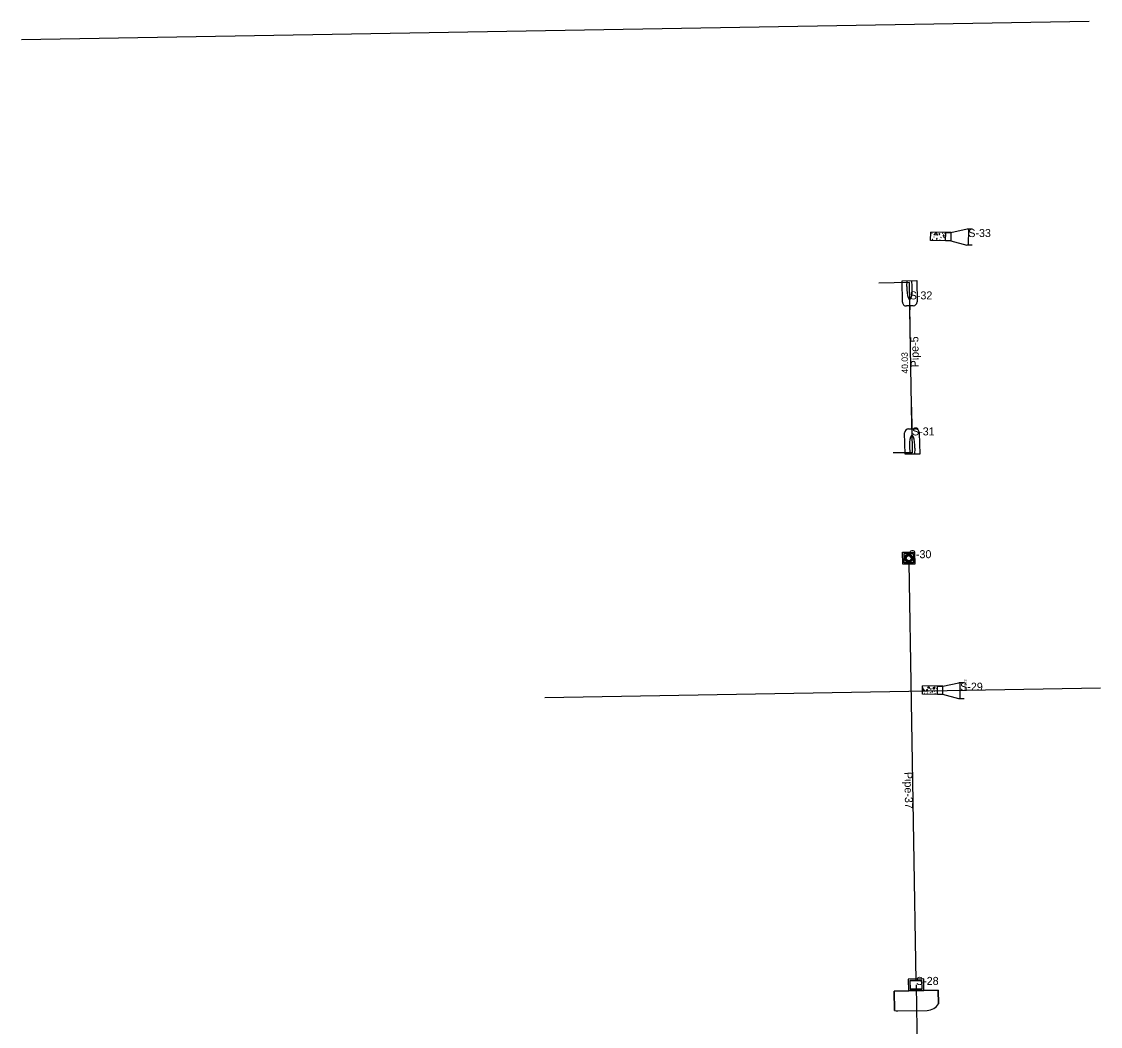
# Model space of a CAD drawing. Extents: x 925371 to 925937, y 853654 to 858024.
# Drawn here: x 925419.2 to 925823.6, y 855352.2 to 855728.9 of the extents above; entities that cross this region are included whole.
import ezdxf

# ---------------------------------------------------------------- set-up
doc = ezdxf.new("R2010")
doc.units = 0
for name, color, linetype in [('DitchPavt', 7, 'Continuous'), ('GPKDrBack_dp', 7, 'Continuous'), ('GPKDrBottom_dp', 7, 'Continuous'), ('GPKDrCellIns_dp', 7, 'Continuous'), ('GPKDrCentroid_dp', 7, 'Continuous'), ('GPKDrFront_dp', 7, 'Continuous'), ('GPKDrPipe_dp', 7, 'Continuous'), ('GPKDrPipeCir_dp', 7, 'Continuous'), ('InletBottomP', 7, 'Continuous'), ('InletClosedFlume', 7, 'Continuous'), ('InletDBI', 7, 'Continuous'), ('Manhole', 7, 'Continuous'), ('MES', 7, 'Continuous'), ('Miscellaneous5', 7, 'Continuous'), ('Miscellaneous6', 7, 'Continuous'), ('NonPlottingEle_dp', 7, 'Continuous'), ('PipeCulvert', 7, 'Continuous'), ('PipeCulvertSS', 7, 'Continuous')]:
    doc.layers.add(name, color=color, linetype=linetype)

msp = doc.modelspace()

# ---------------------------------------------------------------- linework, layer by layer
at = {"layer": 'DitchPavt'}
for p, q in [((925767.56, 855649.81), (925759.96, 855649.94)), ((925760.38, 855649.56), (925760.5, 855649.65)), ((925762.04, 855649.9), (925762.53, 855648.87)), ((925764.63, 855649.52), (925764.41, 855649.61)), ((925765.51, 855649.42), (925765.29, 855649.51)), ((925761.12, 855648.19), (925761.26, 855648.29)), ((925763.97, 855647.93), (925763.75, 855648.02)), ((925765.11, 855647.92), (925764.91, 855648.01)), ((925765.46, 855646.8), (925765.51, 855646.82)), ((925765.51, 855647.69), (925765.52, 855647.7)), ((925757.15, 855477.88), (925756.88, 855478.01)), ((925757.24, 855478.98), (925757.4, 855479.07)), ((925757.53, 855477.11), (925757.68, 855477.22)), ((925758.77, 855477.19), (925758.57, 855477.28)), ((925759.77, 855477.33), (925759.91, 855477.43)), ((925759.84, 855478.54), (925760, 855478.63)), ((925760.03, 855478.81), (925760.18, 855478.9)), ((925761.3, 855478.5), (925761.09, 855478.59)), ((925761.61, 855477.83), (925761.39, 855477.92)), ((925762.11, 855478.84), (925762.26, 855478.97)), ((925751.56, 855365.58), (925746.26, 855365.49)), ((925746.26, 855365.49), (925746.39, 855358.21)), ((925757.39, 855365.68), (925751.56, 855365.58)), ((925747.6, 855358.08), (925758.6, 855358.26))]:
    msp.add_line(p, q, dxfattribs=at)
for points in [[(925765.51, 855646.8), (925759.91, 855646.9), (925759.96, 855649.94)], [(925762.53, 855648.87), (925761.16, 855649.04), (925762.01, 855649.91)], [(925763.11, 855649.18), (925763.22, 855649.15), (925763.32, 855649.23), (925763.29, 855649.34), (925763.24, 855649.42), (925763.17, 855649.42), (925763.06, 855649.38), (925763.01, 855649.29), (925763.06, 855649.2), (925763.11, 855649.18)], [(925760.64, 855647.03), (925760.67, 855647.06), (925760.7, 855647.15), (925760.65, 855647.25), (925760.61, 855647.28), (925760.51, 855647.25), (925760.49, 855647.12), (925760.52, 855647.06), (925760.58, 855647.03), (925760.64, 855647.03)], [(925762.23, 855647.4), (925762.32, 855647.49), (925762.32, 855647.59), (925762.21, 855647.65), (925762.1, 855647.55), (925762.14, 855647.49), (925762.15, 855647.43), (925762.23, 855647.4), (925762.2, 855647.4)], [(925763.25, 855646.84), (925763.47, 855647.14), (925763.57, 855646.83)], [(925764.81, 855648.46), (925764.96, 855648.51), (925765.04, 855648.7), (925764.92, 855648.91), (925764.77, 855648.91), (925764.64, 855648.83), (925764.63, 855648.75), (925764.66, 855648.61), (925764.7, 855648.5), (925764.81, 855648.46)], [(925762.46, 855476.72), (925756.86, 855476.82), (925756.92, 855479.86)], [(925764.51, 855479.73), (925756.92, 855479.86)], [(925759.45, 855478.89), (925758.83, 855479.19), (925759.18, 855479.67), (925759.45, 855478.89)], [(925761.25, 855478.7), (925760.96, 855479.23), (925761.53, 855479.49), (925761.25, 855478.7)], [(925762.33, 855479.77), (925762.32, 855479.75), (925762.36, 855479.69), (925762.42, 855479.66), (925762.48, 855479.66)], [(925762.48, 855479.66), (925762.51, 855479.69), (925762.51, 855479.7)], [(925756.89, 855478.56), (925757.08, 855478.63), (925757.15, 855477.88)], [(925757.74, 855478.17), (925757.79, 855478.3), (925757.72, 855478.3), (925757.65, 855478.27), (925757.68, 855478.19), (925757.74, 855478.17)], [(925758.43, 855478.12), (925758.7, 855478.07), (925758.79, 855478.18), (925758.79, 855478.25), (925758.78, 855478.43), (925758.6, 855478.5), (925758.42, 855478.45), (925758.38, 855478.34), (925758.38, 855478.22), (925758.43, 855478.12)], [(925760.5, 855477.56), (925760.61, 855477.63), (925760.62, 855477.72), (925760.58, 855477.78), (925760.55, 855477.78), (925760.45, 855477.75), (925760.41, 855477.69), (925760.45, 855477.63), (925760.5, 855477.56)], [(925760.87, 855478.88), (925760.93, 855478.93), (925760.96, 855479.01), (925760.93, 855479.07), (925760.87, 855479.09), (925760.79, 855479.07), (925760.71, 855479.04), (925760.74, 855478.94), (925760.78, 855478.88), (925760.87, 855478.88)], [(925761.68, 855476.74), (925761.67, 855476.8), (925761.59, 855476.9), (925761.51, 855476.86), (925761.47, 855476.83), (925761.44, 855476.77), (925761.44, 855476.74)], [(925762.49, 855478.37), (925762.41, 855478.41), (925762.49, 855478.44)], [(925746.26, 855365.49), (925762.76, 855365.77), (925762.85, 855360.76)], [(925746.39, 855358.21), (925746.26, 855365.49)], [(925762.85, 855360.76), (925762.76, 855365.77), (925757.39, 855365.68)]]:
    msp.add_lwpolyline(points, dxfattribs=at)
for centre, start, end in [((925747.52, 855363.08), 256.9322, 270.9573), ((925758.52, 855363.26), 270.9573, 329.9964)]:
    msp.add_arc(centre, 5, start, end, dxfattribs=at)
at = {"layer": 'GPKDrBack_dp'}
for p, q in [((925767.53, 855648.28), (925767.53, 855648.28)), ((925751.95, 855631.82), (925751.95, 855631.82)), ((925753.06, 855566.77), (925753.06, 855566.77)), ((925753.22, 855527.8), (925753.22, 855527.8)), ((925753.47, 855527.8), (925753.47, 855527.8)), ((925764.49, 855478.21), (925764.49, 855478.21)), ((925754.4, 855369.96), (925754.4, 855369.96)), ((925757.36, 855367.84), (925757.36, 855367.84))]:
    msp.add_line(p, q, dxfattribs=at)
at = {"layer": 'GPKDrBottom_dp'}
for p, q in [((925774.03, 855648.17), (925774.03, 855648.17)), ((925752.07, 855624.79), (925752.07, 855624.79)), ((925752.93, 855573.8), (925752.93, 855573.8)), ((925749.94, 855529.49), (925749.94, 855529.49)), ((925751, 855528.47), (925751, 855528.47)), ((925751.69, 855529.52), (925751.69, 855529.52)), ((925751.7, 855528.77), (925751.7, 855528.77)), ((925752.41, 855528.49), (925752.41, 855528.49)), ((925753.44, 855529.55), (925753.44, 855529.55)), ((925749.97, 855527.74), (925749.97, 855527.74)), ((925750, 855525.99), (925750, 855525.99)), ((925750.72, 855527.75), (925750.72, 855527.75)), ((925751.02, 855527.05), (925751.02, 855527.05)), ((925751.72, 855527.77), (925751.72, 855527.77)), ((925751.72, 855527.77), (925751.72, 855527.77)), ((925751.74, 855526.77), (925751.74, 855526.77)), ((925751.75, 855526.02), (925751.75, 855526.02)), ((925752.44, 855527.08), (925752.44, 855527.08)), ((925752.72, 855527.79), (925752.72, 855527.79)), ((925753.47, 855527.8), (925753.47, 855527.8)), ((925753.5, 855526.05), (925753.5, 855526.05)), ((925770.99, 855478.09), (925770.99, 855478.09)), ((925752.16, 855369.26), (925752.16, 855369.26)), ((925752.19, 855367.76), (925752.19, 855367.76)), ((925752.22, 855366.26), (925752.22, 855366.26)), ((925754.41, 855369.29), (925754.41, 855369.29)), ((925754.44, 855367.79), (925754.44, 855367.79)), ((925754.46, 855366.29), (925754.46, 855366.29)), ((925756.66, 855369.33), (925756.66, 855369.33)), ((925756.69, 855367.83), (925756.69, 855367.83)), ((925756.71, 855366.33), (925756.71, 855366.33))]:
    msp.add_line(p, q, dxfattribs=at)
at = {"layer": 'GPKDrCellIns_dp'}
for p, q in [((925774.03, 855648.17), (925774.03, 855648.17)), ((925752.07, 855624.79), (925752.07, 855624.79)), ((925752.94, 855573.8), (925752.94, 855573.8)), ((925751.72, 855527.77), (925751.72, 855527.77)), ((925751.72, 855527.77), (925751.72, 855527.77)), ((925770.99, 855478.09), (925770.99, 855478.09)), ((925754.44, 855367.79), (925754.44, 855367.79))]:
    msp.add_line(p, q, dxfattribs=at)
at = {"layer": 'GPKDrCentroid_dp'}
msp.add_line((925751.72, 855527.77), (925751.72, 855527.77), dxfattribs=at)
at = {"layer": 'GPKDrFront_dp'}
for p, q in [((925775.53, 855648.14), (925775.53, 855648.14)), ((925752.11, 855622.34), (925752.11, 855622.34)), ((925752.9, 855576.25), (925752.9, 855576.25)), ((925749.97, 855527.74), (925749.97, 855527.74)), ((925750.22, 855527.75), (925750.22, 855527.75)), ((925772.49, 855478.06), (925772.49, 855478.06)), ((925751.52, 855367.74), (925751.52, 855367.74)), ((925754.48, 855365.63), (925754.48, 855365.63))]:
    msp.add_line(p, q, dxfattribs=at)
at = {"layer": 'GPKDrPipe_dp'}
for p, q in [((925752.14, 855620.82), (925752.14, 855620.82)), ((925752.87, 855577.77), (925752.87, 855577.77)), ((925751.69, 855529.52), (925751.69, 855529.52)), ((925749.97, 855527.74), (925749.97, 855527.74)), ((925751.75, 855526.02), (925751.75, 855526.02)), ((925753.47, 855527.8), (925753.47, 855527.8)), ((925752.19, 855367.76), (925752.19, 855367.76)), ((925754.41, 855369.29), (925754.41, 855369.29)), ((925754.46, 855366.29), (925754.46, 855366.29)), ((925756.69, 855367.83), (925756.69, 855367.83))]:
    msp.add_line(p, q, dxfattribs=at)
at = {"layer": 'GPKDrPipeCir_dp'}
msp.add_circle((925751.72, 855527.77), 0.958, dxfattribs=at)
at = {"layer": 'InletBottomP'}
for points in [[(925753.93, 855530.06), (925754.01, 855525.56), (925749.51, 855525.48), (925749.43, 855529.98)], [(925749.94, 855529.49), (925753.44, 855529.55), (925753.5, 855526.05), (925750, 855525.99)]]:
    msp.add_lwpolyline(points, close=True, dxfattribs=at)
at = {"layer": 'InletClosedFlume'}
for p, q in [((925767.55, 855649.8), (925767.5, 855646.76)), ((925773.58, 855651.18), (925767.55, 855649.8)), ((925775.58, 855651.14), (925773.58, 855651.18)), ((925774.08, 855651.17), (925773.97, 855645.17)), ((925767.5, 855646.76), (925773.47, 855645.18)), ((925775.47, 855645.14), (925773.47, 855645.18)), ((925764.46, 855476.69), (925764.51, 855479.73)), ((925764.51, 855479.73), (925770.54, 855481.1)), ((925772.54, 855481.06), (925770.54, 855481.1)), ((925770.93, 855475.09), (925771.04, 855481.09)), ((925770.43, 855475.1), (925764.46, 855476.69)), ((925772.43, 855475.06), (925770.43, 855475.1))]:
    msp.add_line(p, q, dxfattribs=at)
for points in [[(925767.51, 855646.76), (925765.51, 855646.8), (925765.56, 855649.84), (925767.56, 855649.81)], [(925764.46, 855476.69), (925762.46, 855476.72), (925762.52, 855479.76), (925764.51, 855479.73)]]:
    msp.add_lwpolyline(points, dxfattribs=at)
at = {"layer": 'InletDBI'}
for p, q in [((925757.32, 855370.01), (925751.49, 855369.91)), ((925751.49, 855369.91), (925751.56, 855365.58)), ((925756.66, 855369.52), (925752.16, 855369.44)), ((925752.16, 855369.44), (925752.22, 855366.07)), ((925756.66, 855369.33), (925752.16, 855369.26)), ((925752.22, 855366.26), (925756.71, 855366.33)), ((925756.72, 855366.14), (925756.66, 855369.52)), ((925757.39, 855365.68), (925757.32, 855370.01)), ((925751.56, 855365.58), (925757.39, 855365.68)), ((925752.22, 855366.07), (925756.72, 855366.14))]:
    msp.add_line(p, q, dxfattribs=at)
at = {"layer": 'Manhole'}
for p, q in [((925750.94, 855528.48), (925750.8, 855528.62)), ((925750.98, 855528.52), (925750.84, 855528.66)), ((925751.68, 855528.82), (925751.67, 855529.02)), ((925751.73, 855528.82), (925751.72, 855529.02)), ((925752.57, 855528.69), (925752.43, 855528.54)), ((925752.61, 855528.65), (925752.47, 855528.51)), ((925750.67, 855527.78), (925750.47, 855527.78)), ((925750.67, 855527.73), (925750.47, 855527.72)), ((925750.97, 855527.03), (925750.83, 855526.89)), ((925751.01, 855527), (925750.87, 855526.85)), ((925751.71, 855526.52), (925751.71, 855526.72)), ((925751.77, 855526.52), (925751.76, 855526.72)), ((925752.6, 855526.88), (925752.46, 855527.02)), ((925752.64, 855526.92), (925752.49, 855527.06)), ((925752.97, 855527.82), (925752.77, 855527.81)), ((925752.97, 855527.77), (925752.77, 855527.76))]:
    msp.add_line(p, q, dxfattribs=at)
for radius in [1.5, 1.25, 1.05, 1]:
    msp.add_circle((925751.72, 855527.77), radius, dxfattribs=at)
at = {"layer": 'MES'}
for p, q in [((925749.2, 855631.77), (925754.7, 855631.87)), ((925749.34, 855623.79), (925749.2, 855631.77)), ((925751.01, 855629.58), (925751.09, 855631.8)), ((925752.97, 855629.62), (925752.82, 855631.83)), ((925754.7, 855631.87), (925754.84, 855623.88)), ((925753.36, 855622.36), (925750.86, 855622.32)), ((925752.11, 855622.34), (925752.14, 855620.82)), ((925752.9, 855576.25), (925752.87, 855577.77)), ((925750.31, 855566.72), (925750.17, 855574.71)), ((925751.65, 855576.23), (925754.14, 855576.27)), ((925755.67, 855574.8), (925755.81, 855566.82)), ((925752.04, 855568.97), (925752.19, 855566.75)), ((925754, 855569.01), (925753.92, 855566.78)), ((925755.81, 855566.82), (925750.31, 855566.72))]:
    msp.add_line(p, q, dxfattribs=at)
for centre, start, end in [((925750.84, 855623.82), 180.9741, 270.9741), ((925753.34, 855623.86), 270.9741, 0.9741), ((925751.67, 855574.73), 90.9741, 180.9741), ((925754.17, 855574.77), 0.9741, 90.9741)]:
    msp.add_arc(centre, 1.5, start, end, dxfattribs=at)
for centre, major_axis in [((925752, 855628.79), (0.07, -4)), ((925753, 855569.8), (-0.07, 4))]:
    msp.add_ellipse(centre, major_axis=major_axis, ratio=0.25, start_param=4.509879, end_param=8.057799, dxfattribs=at)
at = {"layer": 'Miscellaneous5'}
msp.add_line((925819.31, 855728.95), (925419.18, 855722.15), dxfattribs=at)
at = {"layer": 'Miscellaneous6'}
msp.add_line((925823.56, 855478.98), (925615.27, 855475.44), dxfattribs=at)
at = {"layer": 'NonPlottingEle_dp'}
for points in [[(925752.25, 855614.1), (925751.96, 855631.09), (925740.48, 855630.9)], [(925752.76, 855584.33), (925753.05, 855567.33), (925745.92, 855567.21)]]:
    msp.add_lwpolyline(points, dxfattribs=at)
at = {"layer": 'PipeCulvert'}
msp.add_line((925752.87, 855577.77), (925752.14, 855620.82), dxfattribs=at)
at = {"layer": 'PipeCulvertSS'}
for p, q in [((925751.75, 855526.02), (925754.41, 855369.29)), ((925754.44, 855367.79), (925755.33, 855315.37))]:
    msp.add_line(p, q, dxfattribs=at)

# ---------------------------------------------------------------- texts
at = {"layer": 'NonPlottingEle_dp'}
for s, p in [('S-33', (925774.03, 855648.17)), ('S-32', (925752.07, 855624.79)), ('S-31', (925752.94, 855573.8)), ('S-30', (925751.72, 855527.77)), ('S-29', (925770.99, 855478.09)), ('S-28', (925754.44, 855367.79))]:
    msp.add_text(s, height=3, dxfattribs=at).set_placement(p)
for s, height, rotation, p in [('Pipe-5', 3, 90.9741, (925755.5, 855599.35)), ('40.03', 2.4, 90.9741, (925751.49, 855596.99)), ('16.673', 1, 90.9741, (925773.49, 855478.07)), ('Pipe-37', 3, 270.9741, (925750.08, 855447.61))]:
    msp.add_text(s, height=height, rotation=rotation, dxfattribs=at).set_placement(p)

doc.saveas('drawing.dxf')
